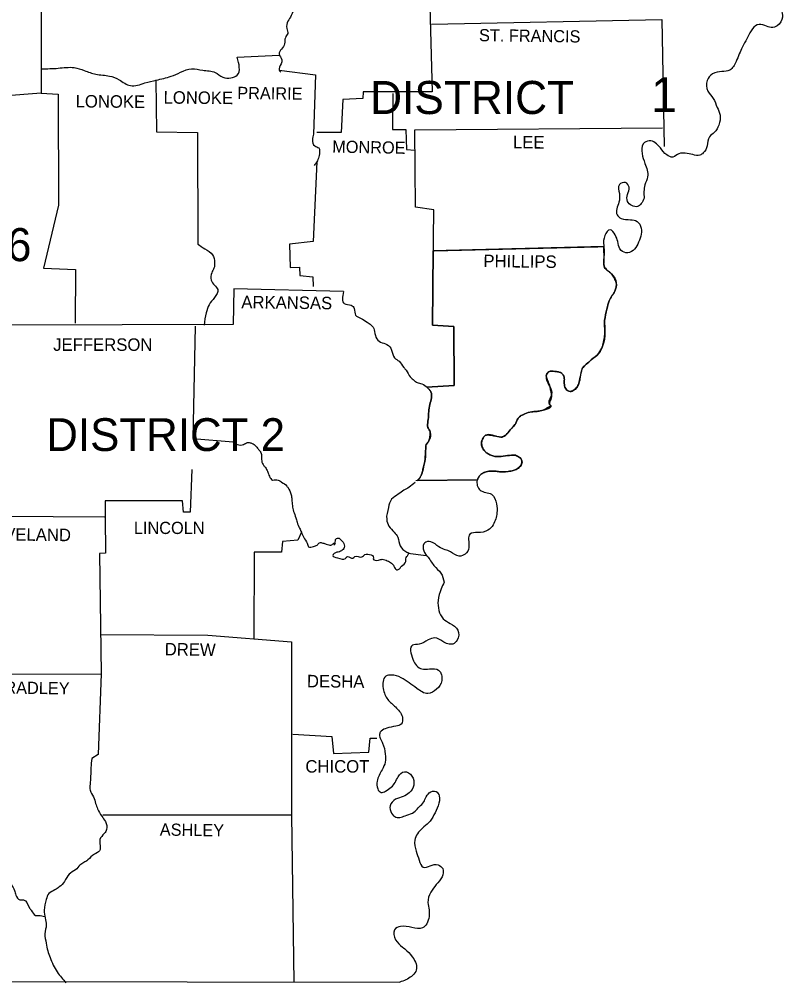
# Model space of a CAD drawing. Extents: x -712 to 3943, y 73 to 2823.
# Drawn here: x 2999.8 to 3257.2, y 1432.7 to 1757.5 of the extents above; entities that cross this region are included whole.
import ezdxf

# ---------------------------------------------------------------- set-up
doc = ezdxf.new("R2010")
doc.units = 0
for name, color, linetype in [('1', 7, 'Continuous'), ('2', 7, 'Continuous'), ('3', 7, 'Continuous'), ('S_MISC_BOUNDARY', 7, 'Continuous')]:
    doc.layers.add(name, color=color, linetype=linetype)

msp = doc.modelspace()

# ---------------------------------------------------------------- linework, layer by layer
at = {"layer": '1'}
msp.add_line((3133.42, 1601.94), (3152.99, 1602.24), dxfattribs=at)
for points in [[(3000.75, 1956.03), (3000.95, 1932.74), (2999.28, 1932.64), (2999.58, 1908.28), (2992.73, 1907.3), (2993.32, 1900.75), (2995.66, 1897.71), (2995.47, 1889.98), (2982.16, 1889.5), (2981.67, 1877.56), (2969.54, 1877.17), (2968.95, 1862.69), (2969.64, 1861.51), (2969.93, 1838.42), (2990.87, 1837.05), (2990.58, 1785.49), (3007.21, 1785), (3007.21, 1732.56), (2994.1, 1731.58), (2993.12, 1720.04), (2971.11, 1719.94)], [(3137.53, 1786.66), (3139, 1733.05), (3115.71, 1732.95), (3115.62, 1730.8), (3108.87, 1730.41), (3108.28, 1719.25), (3100.06, 1719.25)], [(3138.71, 1755.85), (3216.39, 1757.41)], [(3216.39, 1757.41), (3217.18, 1714.56)], [(3073.25, 1744.69), (3087.44, 1745.38)], [(3087.44, 1740.29), (3099.67, 1738.72), (3098.98, 1718.76)], [(3045.86, 1737.06), (3046.05, 1719.55), (3059.85, 1719.25), (3059.95, 1681.68)], [(3007.21, 1732.56), (3012.88, 1732.17), (3012.98, 1694.79), (3007.89, 1673.56), (3018.75, 1673.07), (3018.66, 1655.07)], [(3125.69, 1732.46), (3125.6, 1720.33), (3130.1, 1720.33), (3130.29, 1713.58), (3133.13, 1713.28)], [(3138.71, 1633.54), (3146.34, 1634.03), (3146.24, 1653.9), (3139.1, 1654.38), (3139.49, 1693.23), (3133.33, 1694.11), (3133.13, 1720.23), (3216.59, 1720.82)], [(3100.06, 1709.37), (3098.89, 1682.56), (3090.86, 1681.68), (3091.06, 1673.76), (3094.29, 1673.85), (3094.39, 1671.11), (3098.79, 1670.63), (3098.89, 1667.4)], [(3139.69, 1679.43), (3194.87, 1680.8)], [(3109.06, 1665.64), (3072.08, 1666.61), (3071.88, 1654.58), (2997.03, 1654.29)], [(3059.06, 1653.99), (3058.28, 1616.13), (3071.88, 1615.05)], [(3057.99, 1605.66), (3057.4, 1591.28), (3055.15, 1591.28), (3054.76, 1595.09), (3028.73, 1595.09), (3028.73, 1589.61)], [(2993.9, 1589.91), (3028.54, 1589.71)], [(3028.73, 1589.71), (3028.83, 1577.48), (3026.78, 1577.38), (3027.36, 1536.78)], [(3094.87, 1584.53), (3093.7, 1581.88), (3088.51, 1581.4), (3088.22, 1577.87), (3078.93, 1577.87), (3078.83, 1548.62)], [(3105.83, 1580.22), (3106.13, 1580.51), (3106.42, 1580.81), (3106.42, 1580.81)], [(3027.07, 1550.09), (3063.37, 1549.79), (3091.55, 1547.64)], [(3091.55, 1547.64), (3091.55, 1489.13), (3092.33, 1432.87)], [(2983.14, 1536.68), (3027.36, 1536.78)], [(3027.36, 1536.78), (3026.39, 1509.58), (3024.23, 1508.21)], [(3092.04, 1516.43), (3105.15, 1515.65), (3105.73, 1509.97), (3117.57, 1510.36), (3118.06, 1515.16), (3120.31, 1515.16)], [(2769.26, 1512.61), (2769.46, 1433.46), (3128.04, 1432.87)], [(3027.95, 1489.23), (3091.55, 1489.23)]]:
    msp.add_lwpolyline(points, dxfattribs=at)
for points in [[(3099.86, 1798.01), (3099.37, 1794.79), (3097.52, 1793.91), (3095.36, 1791.75), (3094.87, 1789.8), (3093.11, 1789.01), (3091.45, 1786.96), (3090.37, 1784.12), (3090.37, 1781.19), (3091.06, 1777.86), (3093.5, 1776.98), (3094.68, 1775.02), (3094.48, 1772.97), (3096.83, 1771.6), (3097.22, 1770.42), (3096.83, 1769.15), (3095.75, 1765.53), (3095.85, 1763.09), (3095.66, 1762.01), (3093.02, 1761.32), (3091.45, 1758.68), (3090.37, 1756.82), (3089.98, 1754.38), (3090.28, 1752.62), (3089.49, 1751.25), (3089.2, 1749.19), (3088.22, 1747.43), (3087.34, 1745.77), (3088.32, 1743.81), (3088.03, 1742.44), (3087.44, 1740.29), (3087.93, 1739.6)], [(3252.89, 1794.1), (3253.28, 1791.26), (3251.62, 1788.23), (3251.03, 1785.2), (3251.32, 1782.16), (3248.19, 1780.5), (3245.45, 1778.54), (3247.02, 1776.2), (3249.95, 1774.04), (3252.89, 1772.38), (3254.75, 1770.72), (3255.24, 1766.71), (3255.72, 1764.16), (3256.7, 1760.64), (3257.09, 1758.19), (3255.33, 1755.26), (3253.28, 1754.67), (3251.13, 1755.36), (3248.58, 1755.55), (3246.53, 1753.59), (3245.06, 1750.86), (3243.59, 1748.12), (3242.52, 1745.77), (3241.44, 1743.22), (3239.29, 1740.29), (3236.65, 1739.8), (3233.51, 1739.02), (3231.66, 1736.86), (3231.95, 1733.24), (3233.71, 1730.8), (3235.08, 1727.76), (3236.06, 1725.12), (3235.57, 1721.8), (3234.2, 1719.35), (3232.44, 1717.88), (3231.66, 1714.75), (3230.38, 1712.4), (3229.21, 1711.62), (3226.86, 1711.82), (3224.32, 1712.31), (3222.16, 1712.11), (3220.11, 1711.03), (3218.06, 1711.72), (3215.9, 1714.07), (3214.14, 1715.83), (3212.19, 1716.51), (3210.13, 1715.44), (3209.74, 1712.21), (3210.72, 1708.88), (3211.6, 1704.38), (3210.72, 1701.64), (3210.42, 1697.14)], [(3007.4, 1740.78), (3012.88, 1740.97), (3018.26, 1741.17), (3021.69, 1740.19), (3025.6, 1738.92), (3030.2, 1738.33), (3033.43, 1737.06), (3037.25, 1735.1), (3042.14, 1735.98), (3045.95, 1736.96), (3050.94, 1738.23), (3054.17, 1739.6), (3057.89, 1740.78), (3061.61, 1740.29), (3065.82, 1739.51), (3068.46, 1737.94), (3073.25, 1738.63), (3073.25, 1744.69)], [(3098.98, 1718.76), (3098.59, 1716.81), (3099.37, 1714.75), (3100.74, 1714.07), (3100.94, 1712.11), (3100.45, 1710.15), (3100.06, 1709.37), (3099.18, 1708.2)], [(3210.42, 1697.14), (3208.17, 1694.3), (3204.85, 1696.06), (3204.85, 1698.41), (3205.34, 1700.86), (3204.16, 1702.42), (3202.11, 1701.74), (3202.11, 1698.71), (3201.91, 1695.77), (3201.32, 1691.56), (3202.69, 1690.29), (3205.83, 1689.9), (3208.08, 1689.31), (3209.45, 1687.06), (3209.35, 1684.32), (3208.27, 1681.68), (3206.71, 1679.53), (3204.26, 1678.75), (3202.3, 1680.02), (3201.52, 1682.56), (3200.64, 1684.81), (3198.98, 1686.48), (3197.22, 1684.62), (3196.82, 1681.19), (3196.92, 1678.26), (3196.92, 1674.25), (3199.47, 1671.6), (3201.03, 1668.57), (3200.54, 1665.83), (3198.68, 1662.6), (3197.9, 1659.77), (3197.12, 1655.95), (3197.22, 1651.74), (3196.53, 1647.63), (3195.16, 1644.89), (3192.62, 1642.64), (3190.95, 1641.18), (3189.58, 1639.71), (3188.9, 1636.77), (3188.41, 1634.72), (3186.55, 1632.27), (3185.08, 1632.08), (3183.91, 1633.05), (3183.52, 1634.72), (3183.52, 1636.38), (3182.74, 1638.04), (3180.29, 1638.73), (3178.33, 1638.63), (3177.45, 1637.26), (3178.72, 1633.45), (3179.21, 1631), (3178.53, 1627.67), (3178.92, 1627.28), (3175.4, 1625.42), (3172.56, 1625.13), (3170.21, 1624.44), (3167.96, 1622.98), (3166.88, 1620.82), (3165.32, 1619.06), (3163.95, 1617.4), (3162.09, 1616.62), (3160.04, 1617.01), (3157.3, 1617.3), (3155.73, 1615.35), (3156.22, 1612.51), (3158.08, 1610.85), (3160.82, 1610.06), (3163.66, 1610.26), (3166.4, 1610.55), (3168.94, 1609.18), (3168.45, 1606.54), (3166, 1605.27), (3162.38, 1604.88), (3159.45, 1605.17), (3155.93, 1604.39), (3154.17, 1602.14), (3155.14, 1598.71), (3158.96, 1597.34), (3160.72, 1594.11), (3160.82, 1591.08), (3159.55, 1587.07), (3157.79, 1585.21), (3154.36, 1584.43), (3151.72, 1583.94), (3151.33, 1579.44), (3150.15, 1577.19), (3148.1, 1576.5), (3145.16, 1577.97), (3143.4, 1578.66), (3141.25, 1579.63), (3138.51, 1581.3), (3136.46, 1581), (3137.04, 1576.7), (3137.24, 1576.5), (3139.59, 1573.27), (3141.94, 1570.73), (3143.01, 1567.7)], [(3059.95, 1681.68), (3062.39, 1680.02), (3064.93, 1678.06), (3065.62, 1675.42), (3065.42, 1673.56), (3064.64, 1672), (3064.45, 1669.55), (3065.62, 1667.79), (3066.7, 1666.32), (3065.62, 1663.68), (3063.76, 1661.23), (3062.78, 1658.49), (3062.1, 1654.38)], [(3109.06, 1665.64), (3109.35, 1661.62), (3111.7, 1661.04), (3112.68, 1659.96), (3113.17, 1657.71), (3114.83, 1656.73), (3117.08, 1655.36), (3118.45, 1654.38), (3119.43, 1652.82), (3120.02, 1650.27), (3121.58, 1648.61), (3123.74, 1647.83), (3125.3, 1645.97), (3126.28, 1643.33), (3127.85, 1642.15), (3129.41, 1640.1), (3130.19, 1639.22), (3131.56, 1636.87), (3132.93, 1635.7), (3133.91, 1635.01), (3135.48, 1634.52), (3137.43, 1633.25), (3138.71, 1631.29), (3138.71, 1629.83), (3138.22, 1627.58), (3137.83, 1625.23), (3137.63, 1622.59), (3137.43, 1620.24), (3138.32, 1618.28), (3137.83, 1615.35), (3136.85, 1613.78), (3136.75, 1611.63), (3136.46, 1608.4), (3136.07, 1606.54), (3135.18, 1603.51), (3133.91, 1601.94)], [(3071.88, 1615.05), (3073.35, 1614.07), (3075.4, 1614.17), (3076.77, 1614.76), (3077.85, 1614.66), (3079.32, 1613.78), (3080.3, 1612.61), (3080.98, 1611.73), (3081.47, 1610.36), (3081.47, 1609.08), (3081.96, 1607.32), (3082.55, 1606.64), (3083.33, 1605.37), (3083.82, 1604.19), (3084.11, 1603.41), (3085.19, 1602.14), (3086.17, 1602.24), (3087.05, 1602.14), (3088.22, 1601.45), (3089.98, 1600.08), (3090.28, 1599.69), (3091.45, 1597.15), (3091.65, 1595.58), (3091.84, 1593.53), (3092.23, 1591.57), (3093.02, 1589.42), (3093.41, 1587.95), (3094.29, 1585.9), (3094.87, 1584.53), (3095.66, 1582.76), (3096.83, 1580.81), (3097.32, 1579.63), (3098.98, 1579.73), (3100.16, 1580.22), (3101.04, 1581), (3102.11, 1580.91), (3103.29, 1580.51), (3104.85, 1580.22), (3105.83, 1580.81), (3106.32, 1581.2), (3106.42, 1582.08), (3107.3, 1582.57), (3108.28, 1581.88), (3109.35, 1580.32), (3109.35, 1579.34), (3108.96, 1578.75), (3107.69, 1577.97), (3105.93, 1577.38), (3105.44, 1576.7), (3107.1, 1575.92), (3109.75, 1575.72), (3110.43, 1576.31), (3112.19, 1575.82), (3112.88, 1576.31), (3115.23, 1576.21), (3116.3, 1576.99), (3118.45, 1576.89), (3119.14, 1576.41), (3119.14, 1575.52), (3120.9, 1575.13), (3122.17, 1575.43), (3123.84, 1574.94), (3125.3, 1574.15), (3126.09, 1573.08), (3127.06, 1571.9), (3127.94, 1572.2), (3128.63, 1573.08), (3130.1, 1574.64), (3130.1, 1575.62), (3130.49, 1576.31), (3130.98, 1577.29)], [(3133.23, 1601.35), (3131.17, 1599.69), (3129.41, 1598.71), (3127.55, 1597.34), (3125.3, 1595.68), (3124.23, 1592.84), (3123.64, 1588.93), (3124.42, 1586.58), (3126.18, 1584.53), (3127.36, 1582.86), (3128.24, 1579.93), (3130.39, 1577.87), (3131.08, 1577.58)], [(3143.01, 1567.7), (3142.03, 1565.45), (3140.96, 1561.53), (3141.25, 1558.21), (3142.72, 1555.37), (3145.07, 1553.8), (3147.61, 1551.55), (3147.41, 1548.13), (3145.95, 1546.86), (3142.52, 1547.74), (3139.88, 1548.91), (3137.63, 1548.23), (3134.6, 1546.76), (3132.35, 1546.47), (3132.45, 1541.77), (3135.48, 1538.44), (3138.12, 1538.44), (3141.15, 1538.05), (3142.23, 1534.53), (3140.47, 1531.59), (3137.53, 1530.13), (3133.81, 1531.89), (3131.17, 1533.75), (3128.53, 1535.51), (3125.2, 1536.39), (3123.35, 1536), (3122.47, 1531.89), (3124.03, 1528.17), (3126.57, 1525.63), (3128.92, 1522.3), (3128.53, 1519.85), (3126.77, 1519.17), (3123.64, 1518.48), (3121.78, 1517.51), (3121.29, 1516.72), (3122.27, 1513.4), (3123.15, 1509.78), (3123.15, 1507.04), (3122.07, 1504.49), (3120.41, 1500.58), (3120.61, 1498.03), (3121.78, 1496.86), (3123.25, 1497.25), (3125.2, 1498.62), (3126.48, 1500.19), (3127.55, 1502.14), (3129.61, 1503.81), (3132.15, 1502.34), (3132.74, 1499.31), (3131.27, 1496.67), (3129.22, 1495.49), (3126.67, 1494.51), (3124.81, 1492.36), (3125.3, 1489.82), (3126.77, 1488.45), (3130.39, 1489.13), (3132.84, 1490.21), (3134.21, 1491.58), (3135.87, 1493.24), (3136.75, 1494.9), (3138.02, 1496.67), (3140.27, 1497.15), (3141.35, 1495.69), (3140.96, 1492.36), (3139.59, 1489.23), (3137.73, 1486.59), (3135.67, 1484.73), (3133.13, 1480.72), (3133.62, 1477), (3134.6, 1473.97), (3135.97, 1471.62), (3138.32, 1472.11), (3140.96, 1472.4), (3142.52, 1471.13), (3142.33, 1468.39), (3140.37, 1465.75), (3138.51, 1463.2), (3137.53, 1459.68), (3137.92, 1457.24), (3137.92, 1454.98), (3137.14, 1452.54), (3135.77, 1451.17), (3132.15, 1451.27), (3128.34, 1451.66), (3126.28, 1450.48), (3126.67, 1447.16), (3128.92, 1444.71), (3130.49, 1443.44), (3132.74, 1440.7), (3133.72, 1438.45), (3133.42, 1436.49), (3132.05, 1434.83), (3128.04, 1432.87)], [(3024.23, 1508.21), (3023.94, 1505.18), (3023.84, 1502.34), (3023.65, 1499.6), (3023.65, 1497.55), (3024.82, 1495.3), (3025.51, 1493.14), (3026.19, 1491.28), (3027.56, 1488.84), (3028.83, 1486.98), (3029.22, 1484.34), (3028.44, 1482.97), (3026.97, 1480.91), (3026.87, 1477.19), (3025.11, 1476.02), (3022.86, 1474.06), (3021.59, 1473.18), (3020.22, 1472.3), (3018.75, 1470.74), (3016.6, 1469.27), (3015.04, 1466.82), (3013.28, 1464.96), (3011.81, 1463.99), (3009.75, 1462.71), (3008.87, 1460.76), (3008.19, 1457.14), (3008.48, 1454.5), (3008.87, 1452.15), (3008.38, 1449.21), (3008.87, 1445.98), (3009.36, 1443.44), (3010.14, 1441.19), (3011.22, 1438.65), (3012.59, 1436.3), (3015.53, 1432.68)], [(2926.69, 1485.61), (2928.25, 1486.69), (2929.72, 1487.27), (2931.19, 1486.98), (2932.75, 1486.78), (2934.12, 1486.98), (2935.88, 1486.69), (2937.35, 1485.8), (2939.01, 1485.12), (2940.68, 1485.12), (2942.14, 1485.12), (2943.42, 1484.24), (2945.77, 1484.34), (2947.72, 1485.12), (2949.68, 1485.71), (2952.32, 1486), (2954.67, 1484.34), (2956.33, 1482.97), (2957.7, 1481.4), (2958.68, 1479.64), (2959.76, 1478.66), (2961.52, 1477.98), (2962.89, 1477.68), (2964.55, 1477.19), (2965.43, 1476.8), (2966.21, 1474.94), (2967.49, 1472.4), (2969.93, 1471.52), (2972.96, 1472.69), (2975.41, 1473.38), (2977.17, 1473.97), (2978.25, 1474.36), (2979.23, 1474.46), (2978.93, 1474.65), (2980.11, 1474.94), (2981.18, 1474.16), (2981.87, 1473.09), (2983.04, 1471.52), (2984.12, 1470.15), (2985.19, 1469.66), (2986.27, 1470.25), (2987.74, 1469.76), (2989.01, 1469.27), (2990.48, 1468.88), (2991.75, 1468.78), (2993.41, 1468.39), (2994.69, 1467.7), (2995.86, 1467.02), (2997.03, 1465.75), (2998.21, 1463.79), (2998.6, 1462.23), (2999.97, 1460.66), (3001.24, 1460.66), (3003.1, 1458.12), (3003.78, 1457.14), (3005.25, 1455.38), (3006.33, 1455.38), (3008.38, 1454.98)]]:
    msp.add_spline(points, degree=3, dxfattribs=at)
at = {"layer": '3'}
msp.add_line((3130.78, 1577.48), (3136.95, 1576.7), dxfattribs=at)
at = {"layer": 'S_MISC_BOUNDARY'}
for p, q in [((3196.84, 1680.85), (3139.35, 1679.42)), ((3154.21, 1602.25), (3133.92, 1601.95)), ((3133.92, 1601.95), (3154.21, 1602.25))]:
    msp.add_line(p, q, dxfattribs=at)
for points in [[(3137.21, 1633.45), (3146.34, 1634.03), (3146.24, 1653.9), (3139.1, 1654.38), (3139.35, 1679.42)], [(3139.35, 1679.42), (3139.1, 1654.38), (3146.24, 1653.9), (3146.34, 1634.03), (3137.21, 1633.45)], [(3139.35, 1679.42), (3196.84, 1680.85)]]:
    msp.add_lwpolyline(points, dxfattribs=at)
for points in [[(3196.84, 1680.85), (3196.92, 1678.26), (3196.92, 1674.25), (3197.27, 1673.46), (3197.97, 1672.85), (3198.79, 1672.28), (3199.47, 1671.6), (3199.95, 1670.88), (3200.41, 1670.13), (3201.03, 1668.57), (3200.54, 1665.83), (3200.09, 1665.01), (3199.56, 1664.23), (3199.06, 1663.44), (3198.68, 1662.6), (3197.9, 1659.77), (3197.12, 1655.95), (3197.06, 1654.9), (3197.12, 1653.85), (3197.21, 1652.79), (3197.22, 1651.74), (3196.98, 1649.68), (3196.53, 1647.63), (3195.16, 1644.89), (3192.62, 1642.64), (3190.95, 1641.18), (3189.58, 1639.71), (3188.9, 1636.77), (3188.41, 1634.72), (3188.14, 1634.01), (3187.72, 1633.38), (3187.17, 1632.8), (3186.55, 1632.27), (3185.83, 1631.98), (3185.08, 1632.08), (3183.91, 1633.05), (3183.52, 1634.72), (3183.5, 1635.13), (3183.52, 1635.55), (3183.54, 1635.97), (3183.52, 1636.38), (3183.31, 1637.27), (3183.08, 1637.67), (3182.74, 1638.04), (3182.14, 1638.41), (3181.53, 1638.59), (3180.91, 1638.67), (3180.29, 1638.73), (3179.31, 1638.87), (3178.82, 1638.84), (3178.33, 1638.63), (3177.66, 1638.01), (3177.45, 1637.26), (3177.68, 1636.32), (3178.04, 1635.37), (3178.42, 1634.42), (3178.72, 1633.45), (3178.99, 1632.22), (3179.21, 1631), (3179.18, 1630.17), (3178.94, 1629.34), (3178.67, 1628.5), (3178.53, 1627.67), (3178.61, 1627.55), (3178.77, 1627.45), (3178.91, 1627.37), (3178.92, 1627.28), (3178.16, 1626.7), (3177.3, 1626.18), (3175.4, 1625.42), (3174.69, 1625.3), (3173.97, 1625.26), (3173.26, 1625.22), (3172.56, 1625.13), (3170.21, 1624.44), (3167.96, 1622.98), (3167.63, 1622.47), (3167.41, 1621.9), (3167.19, 1621.33), (3166.88, 1620.82), (3165.32, 1619.06), (3163.95, 1617.4), (3162.09, 1616.62), (3160.04, 1617.01), (3158.67, 1617.26), (3157.98, 1617.33), (3157.64, 1617.33), (3157.3, 1617.3), (3156.74, 1617.06), (3156.3, 1616.57), (3155.97, 1615.96), (3155.73, 1615.35), (3155.64, 1613.91), (3156.22, 1612.51), (3158.08, 1610.85), (3158.75, 1610.53), (3159.43, 1610.27), (3160.82, 1610.06), (3163.66, 1610.26), (3166.4, 1610.55), (3167.1, 1610.47), (3167.76, 1610.16), (3168.38, 1609.71), (3168.94, 1609.18), (3169.24, 1608.57), (3169.22, 1607.84), (3168.45, 1606.54), (3167.88, 1606.11), (3167.29, 1605.74), (3166, 1605.27), (3162.38, 1604.88), (3161.65, 1604.92), (3160.92, 1605.02), (3160.18, 1605.12), (3159.45, 1605.17), (3157.68, 1605.05), (3156.8, 1604.81), (3156.36, 1604.62), (3155.93, 1604.39), (3154.85, 1603.42), (3154.21, 1602.25)], [(3196.42, 1647.25), (3196.53, 1647.63), (3196.98, 1649.68), (3197.13, 1650.71), (3197.22, 1651.74), (3197.21, 1652.79), (3197.12, 1653.85), (3197.06, 1654.9), (3197.12, 1655.95), (3197.9, 1659.77), (3198.68, 1662.6), (3199.06, 1663.44), (3199.56, 1664.23), (3200.09, 1665.01), (3200.54, 1665.83), (3201.01, 1667.19), (3201.03, 1668.57), (3200.93, 1668.97), (3200.79, 1669.37), (3200.41, 1670.13), (3199.95, 1670.88), (3199.47, 1671.6), (3198.79, 1672.28), (3197.97, 1672.85), (3197.27, 1673.46), (3196.92, 1674.25), (3196.91, 1675.25), (3196.92, 1676.25), (3196.93, 1677.25), (3196.92, 1678.26), (3196.84, 1680.85)], [(3178.33, 1634.65), (3178.04, 1635.37), (3177.68, 1636.32), (3177.45, 1637.26), (3177.66, 1638.01), (3178.33, 1638.63), (3178.82, 1638.84), (3179.31, 1638.87), (3180.29, 1638.73), (3180.91, 1638.67), (3181.53, 1638.59), (3182.14, 1638.41), (3182.74, 1638.04), (3183.08, 1637.67), (3183.31, 1637.27), (3183.52, 1636.38), (3183.54, 1635.97), (3183.52, 1635.55), (3183.5, 1635.13), (3183.52, 1634.72), (3183.62, 1633.88), (3183.91, 1633.05), (3184.4, 1632.47), (3184.73, 1632.25), (3185.08, 1632.08), (3185.83, 1631.98), (3186.55, 1632.27), (3187.17, 1632.8), (3187.72, 1633.38), (3188.14, 1634.01), (3188.41, 1634.72), (3188.9, 1636.77), (3189.23, 1638.24), (3189.4, 1638.98), (3189.49, 1639.34), (3189.58, 1639.71), (3190.95, 1641.18), (3192.62, 1642.64), (3195.16, 1644.89), (3196.42, 1647.25)], [(3155.82, 1615.61), (3155.97, 1615.96), (3156.3, 1616.57), (3156.74, 1617.06), (3157.3, 1617.3), (3157.64, 1617.33), (3157.98, 1617.33), (3158.67, 1617.26), (3160.04, 1617.01), (3162.09, 1616.62), (3163.08, 1616.77), (3163.55, 1617.05), (3163.95, 1617.4), (3165.32, 1619.06), (3166.88, 1620.82), (3167.19, 1621.33), (3167.41, 1621.9), (3167.63, 1622.47), (3167.96, 1622.98), (3168.46, 1623.45), (3169.01, 1623.84), (3170.21, 1624.44), (3172.56, 1625.13), (3173.26, 1625.22), (3173.97, 1625.26), (3174.69, 1625.3), (3175.4, 1625.42), (3177.3, 1626.18), (3178.16, 1626.7), (3178.92, 1627.28), (3178.91, 1627.37), (3178.77, 1627.45), (3178.61, 1627.55), (3178.53, 1627.67), (3178.67, 1628.5), (3178.94, 1629.34), (3179.18, 1630.17), (3179.21, 1631), (3178.99, 1632.22), (3178.72, 1633.45), (3178.42, 1634.42), (3178.33, 1634.65)], [(3133.92, 1601.95), (3134.64, 1602.67), (3135.18, 1603.51), (3135.33, 1603.88), (3135.47, 1604.25), (3135.69, 1605.01), (3136.07, 1606.54), (3136.46, 1608.4), (3136.75, 1611.63), (3136.78, 1612.17), (3136.79, 1612.7), (3136.81, 1613.24), (3136.85, 1613.78), (3136.99, 1614.2), (3137.28, 1614.58), (3137.59, 1614.94), (3137.83, 1615.35), (3138.24, 1616.81), (3138.32, 1617.56), (3138.32, 1618.28), (3138.15, 1618.77), (3137.83, 1619.24), (3137.54, 1619.73), (3137.43, 1620.24), (3137.63, 1622.59), (3137.83, 1625.23), (3138.22, 1627.58), (3138.71, 1629.83), (3138.78, 1630.56), (3138.71, 1631.29), (3138.52, 1631.84), (3138.23, 1632.35), (3137.43, 1633.25), (3137.21, 1633.45)], [(3137.21, 1633.45), (3137.43, 1633.25), (3138.23, 1632.35), (3138.52, 1631.84), (3138.71, 1631.29), (3138.78, 1630.56), (3138.71, 1629.83), (3138.22, 1627.58), (3137.83, 1625.23), (3137.63, 1622.59), (3137.43, 1620.24), (3137.54, 1619.73), (3137.83, 1619.24), (3138.15, 1618.77), (3138.32, 1618.28), (3138.32, 1617.56), (3138.24, 1616.81), (3137.83, 1615.35), (3137.59, 1614.94), (3137.28, 1614.58), (3136.99, 1614.2), (3136.85, 1613.78), (3136.81, 1613.24), (3136.79, 1612.7), (3136.78, 1612.17), (3136.75, 1611.63), (3136.46, 1608.4), (3136.07, 1606.54), (3135.69, 1605.01), (3135.47, 1604.25), (3135.33, 1603.88), (3135.18, 1603.51), (3134.64, 1602.67), (3133.92, 1601.95)], [(3154.21, 1602.25), (3154.85, 1603.42), (3155.93, 1604.39), (3156.36, 1604.62), (3156.8, 1604.81), (3157.68, 1605.05), (3159.45, 1605.17), (3160.18, 1605.12), (3160.92, 1605.02), (3161.65, 1604.92), (3162.38, 1604.88), (3164.2, 1604.96), (3165.1, 1605.09), (3166, 1605.27), (3167.29, 1605.74), (3167.88, 1606.11), (3168.45, 1606.54), (3168.92, 1607.14), (3169.08, 1607.48), (3169.22, 1607.84), (3169.24, 1608.57), (3168.94, 1609.18), (3168.38, 1609.71), (3167.76, 1610.16), (3167.1, 1610.47), (3166.4, 1610.55), (3163.66, 1610.26), (3160.82, 1610.06), (3159.43, 1610.27), (3158.75, 1610.53), (3158.08, 1610.85), (3157.07, 1611.56), (3156.63, 1612), (3156.22, 1612.51), (3155.64, 1613.91), (3155.73, 1615.35), (3155.82, 1615.61)]]:
    msp.add_spline(points, degree=3, dxfattribs=at)

# ---------------------------------------------------------------- texts
at = {"layer": '1'}
msp.add_text('1', height=11.74, dxfattribs=at).set_placement((3212.77, 1726.2))
at = {"layer": '2'}
for s, height, rotation, p in [('ST. FRANCIS', 4.1081, 359.2216, (3154.75, 1750.07)), ('PRAIRIE', 4.109, 359.2116, (3073.25, 1730.6)), ('LONOKE', 4.207, 359.4974, (3018.75, 1727.76)), ('LONOKE', 4.207, 359.4974, (3048.4, 1729.04)), ('LEE', 4.207, 359.4327, (3166.2, 1713.97)), ('MONROE', 4.108, 359.0331, (3105.25, 1712.5)), ('PHILLIPS', 4.206, 359.3179, (3156.23, 1673.91)), ('ARKANSAS', 4.206, 359.2678, (3074.62, 1660.06)), ('CLEVELAND', 4.207, 359.3377, (2983.73, 1581.88)), ('DREW', 4.206, 359.2258, (3048.79, 1543.04)), ('DESHA', 4.206, 359.3704, (3096.73, 1532.28)), ('BRADLEY', 4.108, 359.1449, (2991.07, 1530.22)), ('ASHLEY', 4.109, 359.2361, (3047.13, 1482.28))]:
    msp.add_text(s, height=height, rotation=rotation, dxfattribs=at).set_placement(p)
for s, height, p in [('JEFFERSON', 4.207, (3011.22, 1645.68)), ('LINCOLN', 4.109, (3038.42, 1583.94)), ('CHICOT', 4.207, (3096.24, 1503.51))]:
    msp.add_text(s, height=height, dxfattribs=at).set_placement(p)
at = {"layer": '3'}
for s, height, p in [('DISTRICT', 11.154, (3118.06, 1725.51)), ('DISTRICT 6', 11.154, (2922.67, 1675.91)), ('DISTRICT 2', 11.056, (3008.87, 1611.92))]:
    msp.add_text(s, height=height, dxfattribs=at).set_placement(p)

doc.saveas('drawing.dxf')
